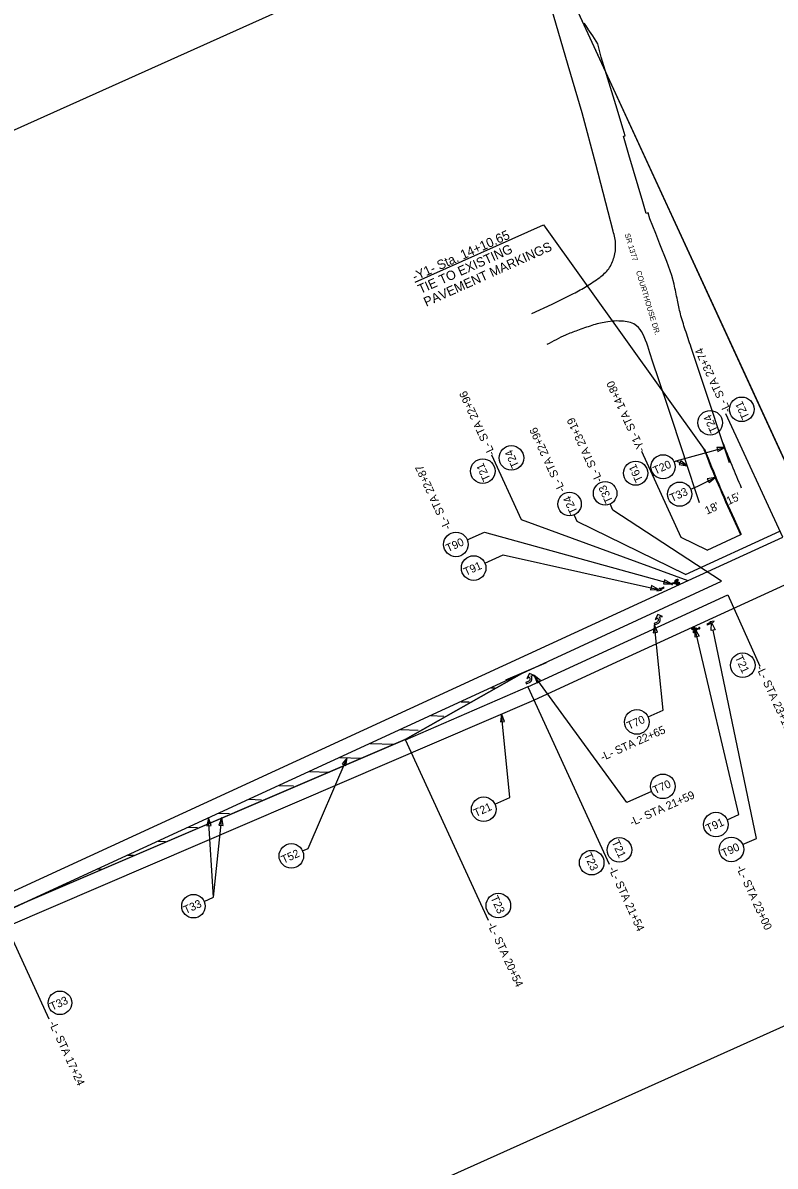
# Model space of a CAD drawing. Extents: x 553958 to 562499, y 493978 to 516388.
# Drawn here: x 555061 to 555625, y 503289 to 504146 of the extents above; entities that cross this region are included whole.
import ezdxf

# ---------------------------------------------------------------- set-up
doc = ezdxf.new("R2010")
doc.units = 0
for name, color, linetype in [('Default', 7, 'Continuous'), ('Prop Approach Slab', 7, 'Continuous'), ('Prop EOT', 7, 'Continuous'), ('Prop EOT Dash', 7, 'Continuous'), ('Prop Erosion Rip Rap Class II Label', 7, 'Continuous'), ('Prop Horizontal Alignment', 7, 'Continuous'), ('Prop Horizontal Alignment Curve and Spiral Data', 7, 'Continuous'), ('Prop Horizontal Alignment Tick Small', 7, 'Continuous'), ('Prop Lane Arrow CELL', 7, 'Continuous'), ('Prop SS Fill Line', 7, 'Continuous'), ('Raster_Level_0', 7, 'Continuous'), ('Scratch_Level_0', 7, 'Continuous'), ('Sheet North Arrow CELL', 7, 'Continuous'), ('Sheet Plan CELL', 7, 'Continuous'), ('Sheet Plot Border Inside CELL', 7, 'Continuous'), ('Sheet Plot Border Outside CELL', 7, 'Continuous')]:
    doc.layers.add(name, color=color, linetype=linetype)

msp = doc.modelspace()

# ---------------------------------------------------------------- linework, layer by layer
at = {"layer": 'Prop Approach Slab'}
for p, q in [((555630.48, 503760.22), (555587.88, 503852.82)), ((555434.67, 503773.3), (555412.42, 503821.67)), ((555554.45, 503760.12), (555524.89, 503824.39)), ((555503.26, 503780.63), (555501.13, 503785.26)), ((555584.55, 503727.26), (555503.26, 503780.63)), ((555559.73, 503727.67), (555434.67, 503773.3)), ((555476.54, 503771.95), (555474.41, 503776.57)), ((555557.65, 503732.22), (555476.54, 503771.95)), ((555573.79, 503750.65), (555554.45, 503760.12)), ((555589.25, 503717.04), (555613.24, 503663.71)), ((555347.44, 503608.62), (555409.69, 503473.31)), ((555043.84, 503478.96), (555080.46, 503399.35))]:
    msp.add_line(p, q, dxfattribs=at)
msp.add_lwpolyline([(555355.08, 503951.29), (555451.09, 503994.4), (555571.71, 503826.09)], dxfattribs=at)
at = {"layer": 'Prop EOT'}
for p, q in [((555557.65, 503732.22), (555628.39, 503764.76)), ((555559.74, 503727.68), (555630.48, 503760.22))]:
    msp.add_line(p, q, dxfattribs=at)
at = {"layer": 'Prop EOT Dash'}
for p, q in [((555434.92, 503658.14), (555064.66, 503487.54)), ((555453.32, 503665.98), (555422.83, 503652.99)), ((555046.51, 503479.45), (555068.41, 503489.21))]:
    msp.add_line(p, q, dxfattribs=at)
msp.add_lwpolyline([(555434.92, 503658.14), (555347.44, 503608.62), (555090.01, 503498.25)], dxfattribs=at)
at = {"layer": 'Prop Erosion Rip Rap Class II Label'}
for points in [[(555736.45, 503590.64), (555435.27, 504245.31), (556565.58, 504822.05), (556936.88, 504379.27), (556608.88, 503978.75)], [(555793.48, 503466.69), (555600.74, 503885.63), (555438.59, 504238.1), (554125.45, 503648.45), (554482.04, 502854.33), (555335.17, 503260.89)]]:
    msp.add_lwpolyline(points, close=True, dxfattribs=at)
at = {"layer": 'Prop Horizontal Alignment'}
for p, q in [((555412.16, 503647.4), (555414.76, 503647.32)), ((555389.45, 503636.96), (555395.62, 503636.75)), ((555366.74, 503626.51), (555376.48, 503626.19)), ((555344.03, 503616.06), (555357.34, 503615.63)), ((555321.31, 503605.61), (555339.1, 503605.03)), ((555298.6, 503595.16), (555314.88, 503594.63)), ((555275.89, 503584.71), (555290.51, 503584.24)), ((555253.18, 503574.26), (555263.96, 503573.91)), ((555230.47, 503563.82), (555239.95, 503563.51)), ((555207.76, 503553.37), (555215.94, 503553.1)), ((555185.04, 503542.92), (555191.93, 503542.7)), ((555162.33, 503532.47), (555167.92, 503532.29)), ((555139.62, 503522.02), (555143.91, 503521.88)), ((555116.91, 503511.57), (555119.9, 503511.48)), ((555094.2, 503501.13), (555095.89, 503501.07))]:
    msp.add_line(p, q, dxfattribs=at)
at = {"layer": 'Prop Horizontal Alignment Curve and Spiral Data'}
for points in [[(555534.08, 503695.51), (555534.49, 503694.6), (555536.85, 503695.66), (555537.27, 503695.88), (555537.58, 503696.08), (555537.88, 503696.36), (555538.11, 503696.65), (555538.27, 503696.91), (555538.46, 503697.31), (555538.56, 503697.63), (555538.65, 503698), (555538.7, 503698.45), (555538.69, 503698.79), (555538.63, 503699.23), (555538.46, 503699.79), (555538.13, 503700.53), (555540.46, 503700.84), (555536.94, 503702.37), (555534.84, 503698.5), (555536.69, 503699.88), (555536.96, 503699.27), (555537.1, 503698.92), (555537.15, 503698.57), (555537.15, 503698.27), (555537.1, 503697.87), (555537.03, 503697.58), (555536.83, 503697.2), (555536.57, 503696.87), (555536.28, 503696.59), (555535.83, 503696.3)], [(555534.08, 503695.51), (555534.49, 503694.6), (555536.85, 503695.66), (555537.27, 503695.88), (555537.57, 503696.08), (555537.88, 503696.36), (555538.11, 503696.65), (555538.27, 503696.91), (555538.46, 503697.31), (555538.56, 503697.63), (555538.65, 503698), (555538.7, 503698.45), (555538.69, 503698.79), (555538.63, 503699.23), (555538.46, 503699.79), (555538.13, 503700.53), (555540.46, 503700.84), (555536.94, 503702.37), (555534.84, 503698.5), (555536.69, 503699.88), (555536.96, 503699.27), (555537.09, 503698.92), (555537.15, 503698.57), (555537.14, 503698.27), (555537.1, 503697.87), (555537.02, 503697.58), (555536.83, 503697.2), (555536.56, 503696.87), (555536.28, 503696.59), (555535.83, 503696.3)], [(555437.9, 503651.26), (555438.31, 503650.35), (555440.67, 503651.41), (555441.09, 503651.63), (555441.4, 503651.83), (555441.7, 503652.11), (555441.93, 503652.4), (555442.09, 503652.66), (555442.28, 503653.06), (555442.38, 503653.38), (555442.47, 503653.75), (555442.52, 503654.2), (555442.51, 503654.54), (555442.45, 503654.98), (555442.28, 503655.55), (555441.95, 503656.28), (555444.28, 503656.59), (555440.76, 503658.12), (555438.66, 503654.25), (555440.51, 503655.63), (555440.78, 503655.02), (555440.91, 503654.67), (555440.97, 503654.32), (555440.96, 503654.02), (555440.92, 503653.62), (555440.84, 503653.33), (555440.65, 503652.95), (555440.38, 503652.62), (555440.1, 503652.34), (555439.65, 503652.05)], [(555437.9, 503651.26), (555438.31, 503650.35), (555440.67, 503651.41), (555441.09, 503651.63), (555441.39, 503651.83), (555441.7, 503652.11), (555441.93, 503652.4), (555442.09, 503652.66), (555442.28, 503653.06), (555442.37, 503653.38), (555442.47, 503653.75), (555442.52, 503654.21), (555442.51, 503654.54), (555442.45, 503654.98), (555442.28, 503655.55), (555441.95, 503656.28), (555444.28, 503656.59), (555440.76, 503658.12), (555438.66, 503654.25), (555440.51, 503655.63), (555440.78, 503655.02), (555440.91, 503654.67), (555440.97, 503654.32), (555440.96, 503654.02), (555440.92, 503653.62), (555440.84, 503653.33), (555440.65, 503652.95), (555440.38, 503652.62), (555440.1, 503652.34), (555439.65, 503652.05)]]:
    msp.add_lwpolyline(points, close=True, dxfattribs=at)
at = {"layer": 'Prop Horizontal Alignment Tick Small'}
for p, q in [((555548.06, 503725.88), (555549.54, 503726.65)), ((555549.49, 503726.28), (555548.52, 503725.78)), ((555550.23, 503725.59), (555549.49, 503726.28)), ((555549.54, 503726.65), (555551.64, 503726.83)), ((555551.66, 503726.59), (555549.68, 503726.43)), ((555549.68, 503726.43), (555550.25, 503725.9)), ((555550.25, 503725.9), (555550.77, 503726.28)), ((555550.68, 503728.38), (555550.78, 503728.16)), ((555550.68, 503728.38), (555550.78, 503728.16)), ((555550.77, 503726.28), (555550.91, 503726.09)), ((555551.11, 503727.41), (555551.21, 503727.19)), ((555551.11, 503727.41), (555551.21, 503727.19)), ((555551.64, 503726.83), (555551.69, 503726.6)), ((555551.68, 503726.15), (555551.78, 503725.92)), ((555551.68, 503726.15), (555551.78, 503725.92)), ((555547.52, 503725.79), (555547.46, 503725.93)), ((555547.52, 503725.79), (555547.46, 503725.93)), ((555547.92, 503724.9), (555547.85, 503725.04)), ((555547.92, 503724.9), (555547.85, 503725.04)), ((555548.27, 503725.63), (555548.06, 503725.88)), ((555549.55, 503725.23), (555548.27, 503725.63)), ((555548.52, 503725.78), (555549.84, 503725.36)), ((555549.84, 503725.36), (555549.55, 503725.23)), ((555550.91, 503726.09), (555550.23, 503725.59)), ((555552.11, 503725.18), (555552.21, 503724.96)), ((555552.11, 503725.18), (555552.21, 503724.96)), ((555563.41, 503692.2), (555563.31, 503692.42)), ((555563.41, 503692.2), (555563.31, 503692.42)), ((555565.68, 503692.02), (555565.96, 503692.15)), ((555566.99, 503691.6), (555565.68, 503692.02)), ((555565.96, 503692.15), (555567.25, 503691.74)), ((555567.6, 503692.48), (555567.66, 503692.34)), ((555567.6, 503692.48), (555567.66, 503692.34)), ((555563.84, 503691.23), (555563.74, 503691.45)), ((555563.84, 503691.23), (555563.74, 503691.45)), ((555563.87, 503690.55), (555563.83, 503690.78)), ((555563.85, 503690.78), (555565.84, 503690.95)), ((555565.98, 503690.72), (555563.87, 503690.55)), ((555564.41, 503689.97), (555564.31, 503690.19)), ((555564.41, 503689.97), (555564.31, 503690.19)), ((555564.61, 503691.29), (555565.29, 503691.79)), ((555564.75, 503691.1), (555564.61, 503691.29)), ((555564.84, 503689), (555564.74, 503689.22)), ((555564.84, 503689), (555564.74, 503689.22)), ((555565.27, 503691.48), (555564.75, 503691.1)), ((555565.84, 503690.95), (555565.27, 503691.48)), ((555565.29, 503691.79), (555566.03, 503691.1)), ((555567.46, 503691.5), (555565.98, 503690.72)), ((555566.03, 503691.1), (555566.99, 503691.6)), ((555567.25, 503691.74), (555567.46, 503691.5)), ((555568, 503691.59), (555568.06, 503691.45)), ((555568, 503691.59), (555568.06, 503691.45))]:
    msp.add_line(p, q, dxfattribs=at)
for points in [[(555539.54, 503720.48), (555538.67, 503720.83), (555541.74, 503722.29), (555541.47, 503722.86), (555538.4, 503721.41), (555538.68, 503722.31), (555536.19, 503720.01)], [(555539.54, 503720.48), (555538.67, 503720.83), (555541.74, 503722.29), (555541.47, 503722.86), (555538.4, 503721.41), (555538.68, 503722.31), (555536.19, 503720.01)], [(555575.86, 503696.82), (555576.73, 503696.46), (555573.65, 503695.02), (555573.92, 503694.45), (555577, 503695.88), (555576.71, 503694.99), (555579.22, 503697.27)], [(555575.86, 503696.82), (555576.73, 503696.46), (555573.65, 503695.02), (555573.92, 503694.45), (555577, 503695.88), (555576.71, 503694.99), (555579.22, 503697.27)]]:
    msp.add_lwpolyline(points, close=True, dxfattribs=at)
for centre, radius, start, end in [((555547.69, 503725.41), 0.563, 114.18158, 294.18158), ((555547.69, 503725.41), 0.563, 114.18158, 294.18158), ((555547.69, 503725.41), 0.41, 294.18158, 114.18158), ((555567.83, 503691.97), 0.41, 114.18158, 294.18158), ((555567.83, 503691.97), 0.563, 294.18158, 114.18158), ((555567.83, 503691.97), 0.563, 294.18158, 114.18158)]:
    msp.add_arc(centre, radius, start, end, dxfattribs=at)
for centre, major_axis, ratio, start_param, end_param in [((555550.94, 503727.78), (1.36, 0.61), 0.435841, 1.570796, 4.712389), ((555550.94, 503727.78), (1.14, 0.51), 0.325967, 1.570796, 4.712389), ((555551.94, 503725.55), (1.36, 0.61), 0.435841, 1.570796, 4.712389), ((555550.94, 503727.78), (1.36, 0.61), 0.435841, 4.712389, 7.853982), ((555550.94, 503727.78), (1.14, 0.51), 0.325967, 4.712389, 7.853982), ((555551.94, 503725.55), (1.36, 0.61), 0.435841, 4.712389, 7.853982), ((555551.94, 503725.55), (1.14, 0.51), 0.325967, 4.712389, 7.853982), ((555551.94, 503725.55), (1.14, 0.51), 0.325967, 1.570796, 4.712389), ((555563.57, 503691.83), (-1.36, -0.61), 0.435841, 4.712389, 7.853982), ((555563.57, 503691.83), (-1.14, -0.51), 0.325967, 4.712389, 7.853982), ((555563.57, 503691.83), (-1.36, -0.61), 0.435841, 1.570796, 4.712389), ((555563.57, 503691.83), (-1.14, -0.51), 0.325967, 1.570796, 4.712389), ((555564.58, 503689.6), (-1.36, -0.61), 0.435841, 4.712389, 7.853982), ((555564.58, 503689.6), (-1.14, -0.51), 0.325967, 4.712389, 7.853982), ((555564.58, 503689.6), (-1.36, -0.61), 0.435841, 1.570796, 4.712389), ((555564.58, 503689.6), (-1.14, -0.51), 0.325967, 1.570796, 4.712389)]:
    msp.add_ellipse(centre, major_axis=major_axis, ratio=ratio, start_param=start_param, end_param=end_param, dxfattribs=at)
at = {"layer": 'Prop Lane Arrow CELL'}
msp.add_line((555439.35, 503648.08), (555347.65, 503608.16), dxfattribs=at)
at = {"layer": 'Prop SS Fill Line'}
msp.add_line((555556.75, 503820.32), (555567.93, 503786.2), dxfattribs=at)
msp.add_arc((556411.4, 504150.03), 885.28, 201.09589, 203.48201, dxfattribs=at)
at = {"layer": 'Raster_Level_0'}
for p, q in [((555434.92, 503658.14), (555584.55, 503727.26)), ((555434.92, 503658.14), (555064.66, 503487.54)), ((555347.44, 503608.62), (555434.92, 503658.14)), ((555434.92, 503658.14), (555434.92, 503658.14)), ((555064.66, 503487.54), (555347.44, 503608.62)), ((555347.08, 503609.39), (555347.08, 503609.39)), ((554619.25, 503282.9), (555064.66, 503487.54))]:
    msp.add_line(p, q, dxfattribs=at)
at = {"layer": 'Scratch_Level_0'}
for points in [[(555503.47, 503989.67), (555499.64, 504004.22), (555490.53, 504039.82), (555480.15, 504078.29), (555469.77, 504113.9), (555458.62, 504151.44), (555447.67, 504188.15), (555436.59, 504224.22)], [(555549.11, 503949.94), (555547.48, 503956.36), (555543.73, 503966.96), (555538.47, 503979.85), (555535.37, 503987.98), (555531, 503998.84), (555529.59, 504003.44), (555528.23, 504003), (555525.56, 504011.7), (555515.09, 504046.92), (555511.24, 504060.74), (555512.29, 504061.19), (555510.85, 504066), (555505.39, 504084.27), (555494.36, 504120.08), (555491.94, 504130), (555488.12, 504136.11), (555484.55, 504141.39)], [(555442.44, 503927.91), (555457.8, 503934.99), (555473.8, 503942.81)], [(555590.53, 503816.04), (555586.13, 503829.44), (555573.62, 503867.18), (555561.83, 503902.55)], [(555556.83, 503820.35), (555556.78, 503820.53), (555544.31, 503858.29), (555532.32, 503893.72)]]:
    msp.add_lwpolyline(points, dxfattribs=at)
msp.add_ellipse((555494.97, 504151.56), major_axis=(0.41, -14.66), ratio=0.986539, start_param=5.091494, end_param=5.451191, dxfattribs=at)
for points in [[(555473.8, 503942.81), (555483.53, 503948.42), (555493.32, 503955.02), (555500.1, 503961.5), (555504.11, 503970.27), (555505.27, 503979.46), (555503.47, 503989.67)], [(555561.83, 503902.55), (555557.47, 503915.65), (555553.82, 503927.71), (555551.6, 503938.02), (555549.11, 503949.94)], [(555532.32, 503893.72), (555525.61, 503912.64), (555521.02, 503918.76), (555511.13, 503922.07), (555497.89, 503921.53), (555487.43, 503918.93), (555476.57, 503915.18), (555467.66, 503911.71), (555453.64, 503904.58)]]:
    msp.add_spline(points, degree=3, dxfattribs=at)
at = {"layer": 'Sheet North Arrow CELL'}
msp.add_line((555573.79, 503750.65), (555599.1, 503762.3), dxfattribs=at)
at = {"layer": 'Sheet Plan CELL'}
msp.add_line((555439.35, 503648.08), (555500.53, 503515.1), dxfattribs=at)
for points in [[(555549.09, 503816.72), (555550.61, 503817.41), (555586.99, 503827.43)], [(555549.09, 503816.72), (555550.61, 503817.41), (555558.91, 503813.73)], [(555561.51, 503796.22), (555566.75, 503798.58), (555579.84, 503805.11)], [(555394.11, 503758.25), (555407.05, 503764.06), (555547.17, 503725.19)], [(555407.28, 503740.89), (555421.1, 503747.03), (555537.43, 503721.16)], [(555529.59, 503625.54), (555540.88, 503630.62), (555534.49, 503694.6)], [(555588.93, 503548.38), (555597.72, 503552.32), (555564.98, 503691.29)], [(555600.47, 503529.97), (555610.74, 503534.44), (555578.34, 503690.52)], [(555532.24, 503569.73), (555513.66, 503561.39), (555444.28, 503656.59)], [(555414.8, 503560.11), (555426.09, 503565.18), (555419.84, 503627.74)], [(555270.62, 503525.15), (555274.85, 503527.05), (555303.98, 503594.99)], [(555196.92, 503487.31), (555203.85, 503490.42), (555210.16, 503550.05)], [(555196.92, 503487.31), (555203.85, 503490.42), (555200.17, 503549.88)]]:
    msp.add_lwpolyline(points, dxfattribs=at)
for points in [[(555581.78, 503824.46), (555586.99, 503827.43), (555580.99, 503827.47)], [(555552.98, 503814.66), (555558.91, 503813.73), (555554.24, 503817.5)], [(555575.35, 503801.13), (555579.84, 503805.11), (555573.96, 503803.91)], [(555541.17, 503725.24), (555547.17, 503725.19), (555542, 503728.23)], [(555531.44, 503720.9), (555537.43, 503721.16), (555532.11, 503723.93)], [(555536.61, 503688.99), (555534.49, 503694.6), (555533.52, 503688.68)], [(555576.82, 503690.21), (555577.19, 503696.2), (555579.87, 503690.83)], [(555564.8, 503685.29), (555564.98, 503691.29), (555567.82, 503686)], [(555448.94, 503652.82), (555444.28, 503656.59), (555446.43, 503650.99)], [(555421.97, 503622.12), (555419.84, 503627.74), (555418.87, 503621.82)], [(555303.12, 503589.05), (555303.98, 503594.99), (555300.26, 503590.27)], [(555202.08, 503544.19), (555200.17, 503549.88), (555198.98, 503544)], [(555211.09, 503544.12), (555210.16, 503550.05), (555208.01, 503544.45)]]:
    msp.add_lwpolyline(points, close=True, dxfattribs=at)
for centre, radius in [((555599.79, 503856.1), 9.22), ((555576.1, 503846.02), 9.22), ((555427.19, 503819.66), 9.22), ((555540.82, 503813.01), 9.06), ((555405.71, 503809.78), 9.22), ((555520.26, 503808.23), 9.06), ((555497.41, 503793.11), 8.82), ((555553.24, 503792.51), 9.06), ((555470.72, 503785.09), 8.82), ((555385.55, 503754.84), 9.22), ((555398.86, 503737.13), 9.22), ((555600.55, 503664.31), 9.22), ((555521.18, 503621.77), 9.22), ((555540.65, 503573.51), 9.22), ((555406.39, 503556.34), 9.22), ((555580.41, 503544.85), 9.22), ((555262.23, 503521.39), 9.19), ((555508.09, 503525.89), 9.22), ((555592.05, 503526.22), 9.22), ((555487.31, 503516.33), 9.22), ((555188.87, 503483.69), 8.82), ((555417.36, 503484.15), 9.22), ((555088.79, 503411.25), 8.82)]:
    msp.add_circle(centre, radius, dxfattribs=at)
at = {"layer": 'Sheet Plot Border Inside CELL'}
for p, q in [((555503, 503665.25), (555657.31, 503736.24)), ((554614.65, 503292.9), (555559.74, 503727.68)), ((555439.35, 503648.08), (555589.25, 503717.04)), ((555443.95, 503638.09), (555503, 503665.25)), ((555048.5, 503468.27), (555444.07, 503638.14))]:
    msp.add_line(p, q, dxfattribs=at)
at = {"layer": 'Sheet Plot Border Outside CELL'}
for p, q in [((555593.54, 503773.78), (555598.87, 503762.19)), ((555593.99, 503773.99), (555599.32, 503762.4)), ((555071.48, 503490.68), (555071.87, 503490.66))]:
    msp.add_line(p, q, dxfattribs=at)
for radius in [900.25, 899.75]:
    msp.add_arc((556411.4, 504150.03), radius, 201.09589, 204.70456, dxfattribs=at)

# ---------------------------------------------------------------- texts
at = {"layer": 'Default'}
msp.add_text('SR 1377     COURTHOUSE DR.', height=4, rotation=286.85, dxfattribs=at).set_placement((555511.98, 503987.34))
at = {"layer": 'Prop Approach Slab'}
for s, p in [('-Y1- Sta. 14+10.65', (555354.73, 503952.07)), ('TIE TO EXISTING', (555359.03, 503942.5)), ('PAVEMENT MARKINGS', (555363.33, 503932.92))]:
    msp.add_text(s, height=7, rotation=24.18158, dxfattribs=at).set_placement(p)
at = {"layer": 'Prop EOT'}
for s, p in [("18'", (555573.74, 503777.08)), ("15'", (555589.87, 503784.33)), ('T91', (555574.5, 503538.9))]:
    msp.add_text(s, height=6, rotation=24.18158, dxfattribs=at).set_placement(p)
at = {"layer": 'Sheet Plan CELL'}
for s, rotation, p in [('-L- STA 23+74', 114.70456, (555591.85, 503855.12)), ('-Y1- STA 14+80', 114.70456, (555527.61, 503825.64)), ('-L- STA 22+96', 114.70456, (555415.14, 503822.92)), ('T21', 114.70456, (555605.79, 503850.24)), ('-L- STA 23+19', 114.70456, (555495.74, 503802.95)), ('T24', 114.70456, (555582.1, 503840.16)), ('-L- STA 22+96', 114.70456, (555467.73, 503795.62)), ('T24', 114.70456, (555433.19, 503813.8)), ('-L- STA 22+87', 114.70456, (555382.11, 503767.46)), ('T21', 114.70456, (555411.71, 503803.92)), ('T61', 114.70456, (555525.95, 503803.05)), ('T20', 24.18158, (555534.94, 503807.08)), ('T33', 114.36029, (555503.36, 503787.25)), ('T33', 24.18158, (555547.36, 503786.58)), ('T24', 114.70456, (555476.88, 503779.23)), ('T90', 24.18158, (555379.64, 503748.9)), ('T91', 24.18158, (555392.95, 503731.18)), ('T21', 294.70456, (555594.55, 503670.17)), ('-L- STA 23+19', 294.70456, (555610.51, 503662.45)), ('T70', 24.18158, (555515.27, 503615.83)), ('-L- STA 22+65', 24.18158, (555495.43, 503592.35)), ('T70', 24.18158, (555534.74, 503567.56)), ('-L- STA 21+59', 24.18158, (555517.37, 503543.51)), ('T21', 24.18158, (555400.48, 503550.4)), ('T21', 294.70456, (555502.1, 503531.75)), ('T90', 24.18158, (555586.14, 503520.27)), ('T52', 24.18158, (555256.35, 503515.46)), ('T23', 294.70456, (555481.32, 503522.19)), ('-L- STA 21+54', 294.70456, (555499.82, 503511.79)), ('-L- STA 23+00', 294.70456, (555595.44, 503512.75)), ('T33', 24.18158, (555182.99, 503477.76)), ('T23', 294.70456, (555411.37, 503490.01)), ('-L- STA 20+54', 294.70456, (555408.98, 503470)), ('T33', 24.18158, (555082.91, 503405.32)), ('-L- STA 17+24', 294.70456, (555080.35, 503396.07))]:
    msp.add_text(s, height=6, rotation=rotation, dxfattribs=at).set_placement(p)

doc.saveas('drawing.dxf')
